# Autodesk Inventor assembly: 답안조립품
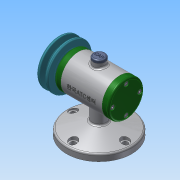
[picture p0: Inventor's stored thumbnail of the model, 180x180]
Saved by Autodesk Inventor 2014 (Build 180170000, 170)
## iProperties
Created: 2018-12
Part Number: 답안조립품
Document SubType Name: Assembly
Designer: sda
Author: sda
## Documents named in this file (15)
- C:\Users\sda\Desktop\481207V1054\답안조립품.iam
- C:\Users\sda\Desktop\481207V1054\본체.ipt
- C:\Users\sda\Desktop\481207V1054\V벨트풀리.ipt
- C:\Users\sda\Desktop\481207V1054\고무캡.ipt
- C:\Users\sda\Desktop\481207V1054\너트 M8.ipt
- 너트 M8.ipt
- C:\Users\sda\Desktop\481207V1054\뒤커버.ipt
- C:\Users\sda\Desktop\481207V1054\베어링 15 x 32 x 9.ipt
- C:\Users\sda\Desktop\481207V1054\볼트 M4 x 12.ipt
- C:\Users\sda\Desktop\481207V1054\스프링와셔 8.ipt
- C:\Users\sda\Desktop\481207V1054\앞커버.ipt
- C:\Users\sda\Desktop\481207V1054\오일 실 15 25 7.ipt
- C:\Users\sda\Desktop\481207V1054\와셔 8x17.ipt
- C:\Users\sda\Desktop\481207V1054\축.ipt
- C:\Users\sda\Desktop\481207V1054\키 3 x 3 x 12.ipt
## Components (2 placed, 2 different names)
1. V벨트풀리:1
2. 고무캡:1 — 각도:3
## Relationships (1: Angle 1)
- 각도:3 [Angle]: 고무캡:1
